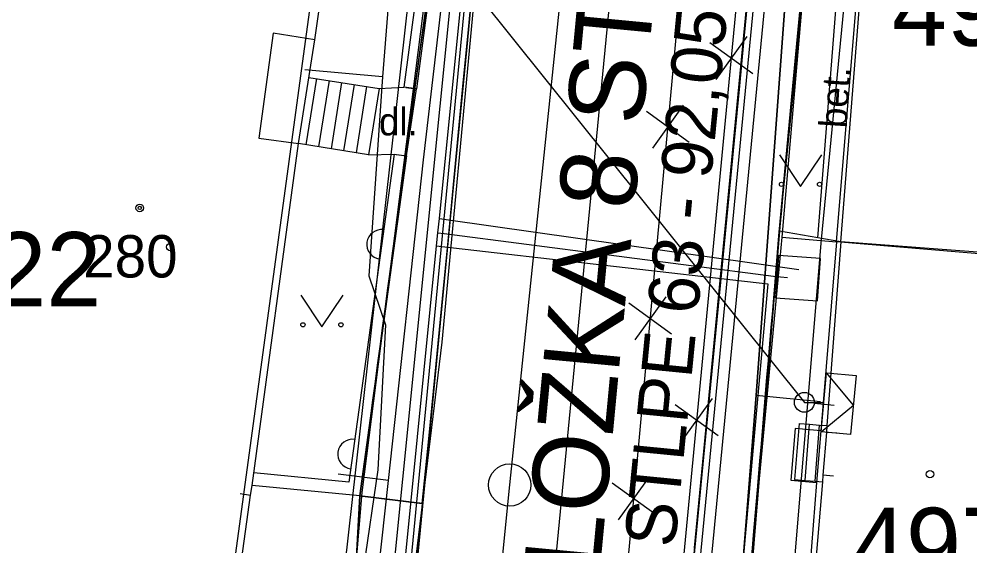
# Model space of a CAD drawing. Extents: x -643342 to -638635, y -1201752 to -1189948.
# Drawn here: x -639509.72 to -639487.27, y -1192781.64 to -1192769.2 of the extents above; entities that cross this region are included whole.
import ezdxf

# ---------------------------------------------------------------- set-up
doc = ezdxf.new("R2010")
doc.units = 0
for name, color, linetype in [('2', 7, 'Continuous'), ('IS_EL_NN_NADZEMNÍ', 7, 'Continuous'), ('IS_EL_NN_PODZEMNÍ', 7, 'Continuous'), ('IS_PLYN_STL', 7, 'Continuous'), ('IS_TELEF_MISTNI_ZAMERENO', 7, 'Continuous'), ('IS_VODOVOD_PRIPOJKA DOMOVNÍ', 7, 'Continuous'), ('IS_VODOVOD_VAS', 7, 'Continuous'), ('K-HRANICE_KN', 7, 'Continuous'), ('K-SLUCKOVE CARY', 7, 'Continuous'), ('K-ČÍSLA_PARCEL', 7, 'Continuous'), ('kanalizace_dešťová_stávající', 7, 'Continuous'), ('N-KAN_DEST_SACHTY-NÁVRH', 7, 'Continuous'), ('N-KAN_DEST_TRASA-NÁVRH', 7, 'Continuous'), ('N-OBVOD STAVBY 06', 7, 'Continuous'), ('N-OSA', 7, 'Continuous'), ('N-rusene_vedeni', 7, 'Continuous'), ('N-SILNICE', 7, 'Continuous'), ('N-SRAFY_PLOCHY', 7, 'Continuous'), ('RWE_STL_RADY', 7, 'Continuous'), ('Z-budovy', 7, 'Continuous'), ('Z-hrany_a_čáry', 7, 'Continuous'), ('Z-popisy', 7, 'Continuous'), ('Z-vchody_vjezdy', 7, 'Continuous'), ('Z-značky', 7, 'Continuous'), ('Z-šachty_poklopy', 7, 'Continuous')]:
    doc.layers.add(name, color=color, linetype=linetype)

msp = doc.modelspace()

# ---------------------------------------------------------------- linework, layer by layer
at = {"layer": 'IS_EL_NN_NADZEMNÍ'}
msp.add_line((-639500.31, -1192766.84), (-639503.93, -1192799.12), dxfattribs=at)
for points in [[(-639490.763, -1192778.947), (-639490.002, -1192778.314), (-639490.635, -1192777.553)], [(-639490.926, -1192778.272), (-639490.458, -1192778.315)]]:
    msp.add_lwpolyline(points, dxfattribs=at)
msp.add_circle((-639491.16, -1192778.25), 0.235, dxfattribs=at)
at = {"layer": 'IS_EL_NN_PODZEMNÍ'}
for p, q in [((-639500.31, -1192766.84), (-639491.16, -1192778.25)), ((-639491.16, -1192778.25), (-639490.7, -1192778.25))]:
    msp.add_line(p, q, dxfattribs=at)
msp.add_lwpolyline([(-639490.763, -1192778.947), (-639490.635, -1192777.553), (-639489.938, -1192777.617), (-639490.066, -1192779.011)], close=True, dxfattribs=at)
at = {"layer": 'IS_PLYN_STL'}
for p, q in [((-639495.52, -1192784.07), (-639493.97, -1192767.19)), ((-639500.989, -1192780.093), (-639502.181, -1192779.947))]:
    msp.add_line(p, q, dxfattribs=at)
msp.add_lwpolyline([(-639501.39, -1192783.75), (-639500.989, -1192780.093), (-639500.16, -1192772.52), (-639499.45, -1192766.45), (-639499.2, -1192762.17), (-639498.55, -1192754.89), (-639497.68, -1192743.88), (-639497.18, -1192733.61), (-639497.87, -1192731.06), (-639499.7, -1192729.08), (-639500.91, -1192728.3), (-639501.94, -1192727.99), (-639507.97, -1192726.09), (-639511.7, -1192724.84), (-639512.15, -1192724.73), (-639515.02, -1192723.8), (-639520.31, -1192722.34), (-639520.46, -1192722.3), (-639520.92, -1192722.11)], dxfattribs=at)
at = {"layer": 'IS_TELEF_MISTNI_ZAMERENO'}
for p, q in [((-639491.29, -1192764.37), (-639492.3, -1192778.08)), ((-639492.3, -1192778.08), (-639491.29, -1192764.37)), ((-639501, -1192768.89), (-639501.13, -1192770.56)), ((-639501.13, -1192770.56), (-639502.97, -1192770.4)), ((-639501.13, -1192770.56), (-639501.45, -1192775.26)), ((-639501.45, -1192775.26), (-639501.06, -1192776.42)), ((-639501.06, -1192776.42), (-639501.24, -1192779.84)), ((-639492.3, -1192778.08), (-639493.24, -1192790.1)), ((-639493.24, -1192790.1), (-639492.3, -1192778.08)), ((-639492.3, -1192778.08), (-639490.78, -1192778.23)), ((-639501.24, -1192779.84), (-639502.02, -1192785.16)), ((-639501.24, -1192779.84), (-639502.02, -1192785.16))]:
    msp.add_line(p, q, dxfattribs=at)
at = {"layer": 'IS_VODOVOD_PRIPOJKA DOMOVNÍ'}
for points in [[(-639499.787, -1192773.906), (-639499.626, -1192773.929), (-639491.289, -1192775.115)], [(-639499.821, -1192774.244), (-639499.673, -1192774.263), (-639491.893, -1192775.269), (-639491.557, -1192775.301)], [(-639499.852, -1192774.557), (-639499.731, -1192774.571), (-639492.02, -1192775.45), (-639493.1, -1192787.48), (-639492.131, -1192787.636)]]:
    msp.add_lwpolyline(points, dxfattribs=at)
at = {"layer": 'IS_VODOVOD_VAS'}
for points in [[(-639513.05, -1192632.38), (-639511.6, -1192653.11), (-639509.94, -1192661.802), (-639509.17, -1192665.92), (-639508.128, -1192674.317), (-639507.037, -1192678.26), (-639504.087, -1192695.682), (-639502.448, -1192705.362), (-639494.166, -1192711.159), (-639494.54, -1192716.007), (-639495.94, -1192729.045), (-639496.55, -1192731.72), (-639496.617, -1192732.012), (-639498.895, -1192762.442), (-639502.42, -1192797.68), (-639508.622, -1192858.606)], [(-639508.361, -1192858.606), (-639507.808, -1192853.178), (-639506.048, -1192835.895), (-639505.024, -1192825.834), (-639502.574, -1192801.785), (-639502.3, -1192799.09), (-639501.659, -1192792.67), (-639499.852, -1192774.557), (-639499.821, -1192774.244), (-639499.787, -1192773.906), (-639498.645, -1192762.458), (-639497.227, -1192743.11), (-639497.188, -1192742.573), (-639497.153, -1192742.104), (-639496.521, -1192733.479), (-639496.454, -1192733.187), (-639495.873, -1192730.664), (-639495.841, -1192730.366)]]:
    msp.add_lwpolyline(points, dxfattribs=at)
at = {"layer": 'K-HRANICE_KN'}
for p, q in [((-639490.57, -1192761.34), (-639491.69, -1192774.35)), ((-639501.61, -1192780.38), (-639499.83, -1192766.37)), ((-639491.69, -1192774.35), (-639492.8, -1192786.16)), ((-639491.69, -1192774.35), (-639490.4, -1192774.46)), ((-639484.62, -1192774.95), (-639490.4, -1192774.46)), ((-639501.94, -1192784.17), (-639501.61, -1192780.38))]:
    msp.add_line(p, q, dxfattribs=at)
at = {"layer": 'K-SLUCKOVE CARY'}
for p, q in [((-639504.82, -1192783.44), (-639502.45, -1192766.04)), ((-639490.4, -1192774.46), (-639489.8, -1192767.24)), ((-639490.4, -1192774.46), (-639490.77, -1192778.92)), ((-639491.38, -1192778.87), (-639491.48, -1192780.09)), ((-639490.77, -1192778.92), (-639491.38, -1192778.87)), ((-639490.77, -1192778.92), (-639490.87, -1192780.14)), ((-639491.48, -1192780.09), (-639490.87, -1192780.14)), ((-639490.87, -1192780.14), (-639491.37, -1192786.28))]:
    msp.add_line(p, q, dxfattribs=at)
at = {"layer": 'K-ČÍSLA_PARCEL'}
for centre in [(-639506.149, -1192774.581), (-639488.191, -1192779.947)]:
    msp.add_circle(centre, 0.0875, dxfattribs=at)
at = {"layer": 'kanalizace_dešťová_stávající'}
msp.add_lwpolyline([(-639500.838, -1192858.606), (-639498.4, -1192827.95), (-639495.47, -1192797.17), (-639492.53, -1192766.39), (-639489.24, -1192732.18), (-639488.56, -1192730.68), (-639487.73, -1192718.33)], dxfattribs=at)
at = {"layer": 'N-KAN_DEST_SACHTY-NÁVRH'}
msp.add_circle((-639498.124, -1192780.201), 0.5, dxfattribs=at)
at = {"layer": 'N-KAN_DEST_TRASA-NÁVRH'}
msp.add_lwpolyline([(-639498.884, -1192834.039), (-639503.116, -1192829.951), (-639498.124, -1192780.201), (-639493.988, -1192740.511), (-639490.998, -1192720.223)], dxfattribs=at)
at = {"layer": 'N-OBVOD STAVBY 06'}
for points in [[(-639501.67, -1192780.46), (-639501.67, -1192780.46), (-639500.56, -1192772.43), (-639500.37, -1192770.844), (-639499.75, -1192766.35), (-639501.075, -1192766.21), (-639500.65, -1192762.336), (-639499.361, -1192762.432), (-639499.064, -1192758.144), (-639498.745, -1192753.539), (-639498.595, -1192751.279), (-639498.595, -1192751.279), (-639499.424, -1192751.305), (-639499.616, -1192745.247), (-639499.725, -1192743.019), (-639499.783, -1192741.836), (-639500.319, -1192735.379)], [(-639487.47, -1192738.74), (-639488.76, -1192754.221), (-639488.809, -1192754.786), (-639489.29, -1192754.75), (-639489.321, -1192755.15), (-639488.844, -1192755.192), (-639488.935, -1192756.241), (-639489.47, -1192756.2), (-639489.48, -1192756.62), (-639488.976, -1192756.658), (-639489.515, -1192761.605), (-639489.908, -1192765.631), (-639490.17, -1192765.614), (-639490.19, -1192765.92), (-639489.939, -1192765.944), (-639490.045, -1192767.036), (-639490.25, -1192767.02), (-639490.29, -1192767.32), (-639490.075, -1192767.34), (-639490.106, -1192767.661), (-639490.763, -1192774.407), (-639491.607, -1192784.497)], [(-639501.849, -1192783.793), (-639501.849, -1192783.793), (-639501.67, -1192780.46), (-639501.67, -1192780.46)]]:
    msp.add_lwpolyline(points, dxfattribs=at)
at = {"layer": 'N-OSA'}
msp.add_lwpolyline([(-639495.549, -1192766.512), (-639499.658, -1192808.961)], dxfattribs=at)
at = {"layer": 'N-rusene_vedeni'}
for p, q in [((-639493.393, -1192769.752), (-639492.379, -1192770.484)), ((-639492.52, -1192769.611), (-639493.252, -1192770.625)), ((-639494.022, -1192771.23), (-639494.753, -1192772.244)), ((-639494.894, -1192771.371), (-639493.881, -1192772.103)), ((-639494.438, -1192775.759), (-639495.169, -1192776.773)), ((-639495.31, -1192775.9), (-639494.297, -1192776.632)), ((-639494.21, -1192778.303), (-639493.196, -1192779.035)), ((-639493.337, -1192778.162), (-639494.069, -1192779.176)), ((-639494.828, -1192780.012), (-639495.56, -1192781.026)), ((-639495.701, -1192780.153), (-639494.687, -1192780.885))]:
    msp.add_line(p, q, dxfattribs=at)
at = {"layer": 'N-SILNICE'}
for p, q in [((-639498.934, -1192766.184), (-639503.042, -1192808.633)), ((-639498.784, -1192766.199), (-639502.893, -1192808.648)), ((-639492.314, -1192766.825), (-639496.423, -1192809.274)), ((-639492.165, -1192766.839), (-639496.274, -1192809.288)), ((-639501.67, -1192780.46), (-639501.88, -1192784.36)), ((-639501.67, -1192780.46), (-639500.182, -1192780.64))]:
    msp.add_line(p, q, dxfattribs=at)
for centre, radius, start, end in [((-638654.028, -1192849.484), 841.096, 173.995633, 175.721181), ((-637018.996, -1193111.101), 2504.594, 172.088263, 172.414023)]:
    msp.add_arc(centre, radius, start, end, dxfattribs=at)
at = {"layer": 'N-SRAFY_PLOCHY'}
for p, q in [((-639498.87, -1192767.079), (-639499.139, -1192769.86)), ((-639493.753, -1192781.684), (-639492.4, -1192767.706)), ((-639499.963, -1192767.918), (-639500.256, -1192770.014)), ((-639499.098, -1192769.444), (-639498.973, -1192768.144)), ((-639499.237, -1192770.871), (-639499.098, -1192769.444)), ((-639499.139, -1192769.86), (-639499.436, -1192772.932)), ((-639500.256, -1192770.014), (-639500.607, -1192772.574)), ((-639499.437, -1192772.938), (-639499.237, -1192770.871)), ((-639500.607, -1192772.574), (-639500.958, -1192775.16)), ((-639499.436, -1192772.932), (-639499.69, -1192775.561)), ((-639499.582, -1192774.442), (-639499.437, -1192772.938)), ((-639499.714, -1192775.801), (-639499.582, -1192774.442)), ((-639500.958, -1192775.16), (-639501.432, -1192778.714)), ((-639499.69, -1192775.561), (-639500.023, -1192778.998)), ((-639499.863, -1192777.344), (-639499.714, -1192775.801)), ((-639500.026, -1192779.029), (-639499.863, -1192777.344)), ((-639501.432, -1192778.714), (-639501.67, -1192780.46)), ((-639500.023, -1192778.998), (-639500.414, -1192783.036)), ((-639500.192, -1192780.639), (-639500.026, -1192779.029)), ((-639501.67, -1192780.46), (-639501.849, -1192783.789)), ((-639501.67, -1192780.46), (-639500.192, -1192780.639)), ((-639500.182, -1192780.64), (-639501.67, -1192780.46)), ((-639500.5, -1192783.92), (-639500.182, -1192780.64))]:
    msp.add_line(p, q, dxfattribs=at)
for points in [[(-639492.003, -1192777.28), (-639491.761, -1192774.317), (-639491.434, -1192770.776), (-639491.122, -1192767.528), (-639490.751, -1192763.823), (-639490.418, -1192760.597), (-639490.15, -1192757.973), (-639489.952, -1192756.034), (-639489.698, -1192753.548), (-639489.377, -1192750.419)], [(-639491.02, -1192753.104), (-639491.228, -1192755.364), (-639491.425, -1192757.521), (-639491.638, -1192759.777), (-639491.738, -1192760.831), (-639491.808, -1192761.568), (-639491.874, -1192762.256), (-639491.938, -1192762.929), (-639492.007, -1192763.641), (-639492.081, -1192764.412), (-639492.145, -1192765.08), (-639492.256, -1192766.226), (-639492.395, -1192767.465), (-639492.556, -1192769.325), (-639492.697, -1192770.775), (-639492.822, -1192772.065), (-639493.145, -1192775.409), (-639493.435, -1192778.406), (-639493.747, -1192781.625), (-639494.005, -1192784.291)], [(-639492.78, -1192786.73), (-639492.363, -1192781.385), (-639492.003, -1192777.28)]]:
    msp.add_lwpolyline(points, dxfattribs=at)
at = {"layer": 'RWE_STL_RADY'}
msp.add_lwpolyline([(-639497.844, -1192828.492), (-639491.5, -1192762.757), (-639493.022, -1192762.61), (-639492.143, -1192753.805), (-639490.591, -1192738.259)], dxfattribs=at)
at = {"layer": 'Z-budovy'}
for p, q in [((-639502.73, -1192769.69), (-639502.218, -1192766.073)), ((-639490.3, -1192774.46), (-639489.74, -1192767.37)), ((-639503.718, -1192769.533), (-639504.053, -1192772.014)), ((-639502.73, -1192769.69), (-639503.718, -1192769.533)), ((-639503.12, -1192772.14), (-639502.73, -1192769.69)), ((-639504.053, -1192772.014), (-639503.12, -1192772.14)), ((-639504.21, -1192780.21), (-639503.12, -1192772.14)), ((-639490.3, -1192774.46), (-639490.628, -1192778.799)), ((-639485.314, -1192774.837), (-639490.3, -1192774.46)), ((-639490.64, -1192778.96), (-639490.72, -1192779.97)), ((-639490.628, -1192778.799), (-639490.64, -1192778.96)), ((-639490.72, -1192779.97), (-639490.733, -1192780.127)), ((-639504.25, -1192780.44), (-639504.21, -1192780.21)), ((-639490.733, -1192780.127), (-639491.27, -1192786.42)), ((-639504.63, -1192783.15), (-639504.25, -1192780.44))]:
    msp.add_line(p, q, dxfattribs=at)
at = {"layer": 'Z-hrany_a_čáry'}
for p, q in [((-639491.75, -1192774.21), (-639488.147, -1192738.494)), ((-639497.82, -1192756.55), (-639499.73, -1192776.83)), ((-639491.44, -1192757.6), (-639493.35, -1192777.33)), ((-639499.76, -1192766.56), (-639500.33, -1192770.85)), ((-639500.1, -1192766.83), (-639500.627, -1192770.809)), ((-639490.29, -1192767.32), (-639490.849, -1192774.365)), ((-639502.691, -1192770.605), (-639502.94, -1192772.169)), ((-639502.871, -1192770.576), (-639501.21, -1192770.84)), ((-639502.395, -1192770.652), (-639502.644, -1192772.216)), ((-639502.099, -1192770.699), (-639502.348, -1192772.263)), ((-639501.802, -1192770.746), (-639502.051, -1192772.31)), ((-639501.506, -1192770.793), (-639501.755, -1192772.357)), ((-639501.21, -1192770.84), (-639501.459, -1192772.404)), ((-639501.21, -1192770.84), (-639500.627, -1192770.809)), ((-639500.33, -1192770.85), (-639500.627, -1192770.809)), ((-639501.459, -1192772.404), (-639503.12, -1192772.14)), ((-639500.857, -1192772.389), (-639501.928, -1192780.133)), ((-639500.56, -1192772.43), (-639501.67, -1192780.46)), ((-639501.459, -1192772.404), (-639500.857, -1192772.389)), ((-639500.857, -1192772.389), (-639500.56, -1192772.43)), ((-639491.75, -1192774.21), (-639492.78, -1192786.73)), ((-639490.3, -1192774.46), (-639491.75, -1192774.21)), ((-639499.73, -1192776.83), (-639500.68, -1192784.66)), ((-639493.35, -1192777.33), (-639495.68, -1192801.91)), ((-639491.28, -1192778.75), (-639491.393, -1192780.071)), ((-639491.28, -1192778.75), (-639491.039, -1192778.768)), ((-639491.144, -1192780.092), (-639491.039, -1192778.768)), ((-639491.039, -1192778.768), (-639490.8, -1192778.786)), ((-639490.905, -1192780.108), (-639490.8, -1192778.786)), ((-639490.8, -1192778.786), (-639490.628, -1192778.799)), ((-639501.928, -1192780.133), (-639504.17, -1192779.912)), ((-639491.393, -1192780.071), (-639491.144, -1192780.092)), ((-639491.144, -1192780.092), (-639490.905, -1192780.108)), ((-639490.905, -1192780.108), (-639490.733, -1192780.127)), ((-639501.67, -1192780.46), (-639504.21, -1192780.21))]:
    msp.add_line(p, q, dxfattribs=at)
for centre in [(-639501.152, -1192774.519), (-639501.837, -1192779.472)]:
    msp.add_arc(centre, 0.35, 82.1259, 262.1259, dxfattribs=at)
at = {"layer": 'Z-vchody_vjezdy'}
for p, q in [((-639500.577, -1192770.814), (-639500.33, -1192770.85)), ((-639500.56, -1192772.43), (-639500.33, -1192770.85)), ((-639500.807, -1192772.394), (-639500.56, -1192772.43)), ((-639490.64, -1192778.96), (-639490.72, -1192779.97)), ((-639490.391, -1192778.98), (-639490.64, -1192778.96)), ((-639490.471, -1192779.99), (-639490.72, -1192779.97)), ((-639504.63, -1192783.15), (-639504.25, -1192780.44)), ((-639504.498, -1192780.405), (-639504.25, -1192780.44))]:
    msp.add_line(p, q, dxfattribs=at)
at = {"layer": 'Z-značky'}
for p, q in [((-639491.751, -1192772.402), (-639491.251, -1192773.152)), ((-639491.251, -1192773.152), (-639490.751, -1192772.402)), ((-639503.062, -1192775.719), (-639502.562, -1192776.469)), ((-639502.562, -1192776.469), (-639502.062, -1192775.719))]:
    msp.add_line(p, q, dxfattribs=at)
for centre, radius in [((-639491.701, -1192773.102), 0.05), ((-639490.802, -1192773.102), 0.05), ((-639506.868, -1192773.658), 0.09), ((-639506.868, -1192773.658), 0.0398), ((-639503.012, -1192776.419), 0.05), ((-639502.113, -1192776.419), 0.05)]:
    msp.add_circle(centre, radius, dxfattribs=at)
at = {"layer": 'Z-šachty_poklopy'}
for p, q in [((-639491.774, -1192774.786), (-639491.844, -1192775.784)), ((-639490.776, -1192774.856), (-639491.774, -1192774.786)), ((-639490.846, -1192775.854), (-639490.776, -1192774.856)), ((-639491.844, -1192775.784), (-639490.846, -1192775.854))]:
    msp.add_line(p, q, dxfattribs=at)

# ---------------------------------------------------------------- texts
at = {"layer": '2'}
msp.add_text('PŘELOŽKA 8 STL', height=1.8, rotation=84.5748, dxfattribs=at).set_placement((-639496.463, -1192787.181))
at = {"layer": 'K-ČÍSLA_PARCEL'}
for s, p in [('495', (-639489.09, -1192769.83)), ('22', (-639510.377, -1192775.98)), ('497', (-639490.06, -1192782.49))]:
    msp.add_text(s, height=1.75, dxfattribs=at).set_placement(p)
at = {"layer": 'RWE_STL_RADY'}
msp.add_text('STLPE 63 - 92,05 m', height=1.2, rotation=84.3846, dxfattribs=at).set_placement((-639494.223, -1192781.7))
at = {"layer": 'Z-popisy'}
msp.add_text('bet.', height=0.65, rotation=86.3104, dxfattribs=at).set_placement((-639490.161, -1192771.789))
for s, height, p in [('dl.', 0.65, (-639501.214, -1192771.947)), ('280', 1, (-639508.206, -1192775.301))]:
    msp.add_text(s, height=height, dxfattribs=at).set_placement(p)

doc.saveas('drawing.dxf')
